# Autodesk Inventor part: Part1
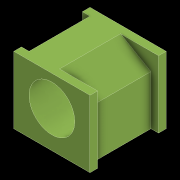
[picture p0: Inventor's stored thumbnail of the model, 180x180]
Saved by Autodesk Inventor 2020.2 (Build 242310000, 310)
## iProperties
Category: 8
Manager: PART
Company: 11
Created: 2020-10
Part Number: Part1
Material: Generic
Document SubType Name: Modeling
Designer: Apardo
Density: 1 g/cm^3
Appearance: Olive Green
Vendor: 8
Description: POSITION 8
Project: PLATE ROLLING MACHINE
Cost Center: 1
Engineer: STEEL C45
Stock Number: 1.7
Engr Approved By: D. JAEGER
Author: Apardo
Revision Number: 1.0
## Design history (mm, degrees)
sketch "Sketch1"
  geometry: L1 (-12.5, -11)-(12.5, -11); L2 (12.5, -11)-(12.5, 11); L3 (12.5, 11)-(-12.5, 11); L4 (-12.5, 11)-(-12.5, -11); L5 (-12.5, -11)-(12.5, 11); L6 (12.5, -11)-(-12.5, 11); 1 further point
  constraints: 12 end point, 2 midpoint, 2 parallel, 1 horizontal, 1 perpendicular
  dimensions: "d0" = 25 distance of L3.end L2.end; "d1" = 22 distance of L2.end L1.end
extrude "Extrusion1" new body sketch "Sketch1" stored distance "d2" = 25; taper "d3" = 0 deg
sketch "Sketch2"
  geometry: L1 (12.5, -11)-(12.5, 11) reference; L2 (-12.5, -11)-(12.5, -11) reference; 2 further points
  dimensions: "d4" = 12.5 distance from line of L1 point (0, 1); "d5" = 12 distance from line of L2 point (0, 1)
hole "Hole1" sketch "Sketch2" at (0, 1) diameter "d6" = 15.02; stored, may be unused: countersink angle "d10" = 90 deg, drill point angle "d12" = 118 deg; dims "d7" = 6, "d8" = 4, "d9" = 2, "d11" = 20
sketch "Sketch3"
  geometry: L1 (-10, -10)-(-17.059, -10); L2 (-17.059, -10)-(-17.059, 10); L3 (-17.059, 10)-(-10, 10); L4 (-10, 10)-(-10, -10); L5 (18.235, -10)-(10, -10); L6 (10, -10)-(10, 10); L7 (10, 10)-(18.235, 10); L8 (18.235, 10)-(18.235, -10); 1 further point
  constraints: 16 end point, 5 parallel, 2 horizontal, 2 perpendicular, 1 collinear
  dimensions: "d13" = 20 distance of L3.end L1.start; "d14" = 20 distance between parallel lines of L4 L6 (= d13); "d15" = 10 distance from line of point (0, 0) L6 (= 0.5 x d14); "d16" = 10 distance from line of point (0, 0) L1 (= 0.5 x d13)
extrude "Extrusion2" cut sketch "Sketch3" stored distance "d17" = 26; taper "d18" = 0 deg
sketch "Sketch4"
  geometry: L1 (0, 0)-(0, 17); L2 (0, 11)-(10.863, 4.728); L3 (10.863, 4.728)-(11.125, 15.5); L4 (11.125, 15.5)-(0, 15.5); L5 (0, 15.5)-(0, 11); L6 (-12.5, 11)-(12.5, 11) reference; C1 r 7.51 at (0, 1) reference
  constraints: 10 end point, 2 point on line, 1 collinear, 1 midpoint, 1 perpendicular, 1 vertical
  dimensions: "d19" = 120 deg angle of L1 L2
extrude "Extrusion3" cut sketch "Sketch4" stored distance "d21" = 20; taper "d22" = 0 deg
body "Solid1"
